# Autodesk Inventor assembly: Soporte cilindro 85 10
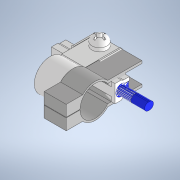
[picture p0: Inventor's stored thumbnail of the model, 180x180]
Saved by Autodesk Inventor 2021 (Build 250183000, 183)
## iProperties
Created: 2021-03
Part Number: Soporte cilindro 85 10
Document SubType Name: Assembly
Designer: ATOUZA
Author: ATOUZA
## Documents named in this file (4)
- D:\01 Paralaia\Grupos de Traballo\GT Maquetas\CAD 3D\E_AlimentaciónV1\Soportes Reed DM9B\Soporte cilindro 85 10.iam
- D:\01 Paralaia\Grupos de Traballo\GT Maquetas\CAD 3D\E_AlimentaciónV1\Soportes Reed DM9B\D-M9B_C85.ipt
- D:\01 Paralaia\Grupos de Traballo\GT Maquetas\CAD 3D\E_AlimentaciónV1\Soportes Reed DM9B\Soporte cilindro Bore10.ipt
- D:\01 Paralaia\Grupos de Traballo\GT Maquetas\CAD 3D\E_AlimentaciónV1\Soportes Reed DM9B\D-M9B.ipt
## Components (3 placed, 3 different names)
1. D-M9B_C85:1 — Nivelación:1, Nivelación:2, Nivelación:3
2. Soporte cilindro Bore10:1
3. D-M9B:1 — Nivelación:1, Nivelación:2, Nivelación:3
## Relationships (3: Flush 3)
- Nivelación:1 [Flush]: D-M9B_C85:1 ↔ D-M9B:1
- Nivelación:2 [Flush]: D-M9B_C85:1 ↔ D-M9B:1
- Nivelación:3 [Flush]: D-M9B_C85:1 ↔ D-M9B:1
